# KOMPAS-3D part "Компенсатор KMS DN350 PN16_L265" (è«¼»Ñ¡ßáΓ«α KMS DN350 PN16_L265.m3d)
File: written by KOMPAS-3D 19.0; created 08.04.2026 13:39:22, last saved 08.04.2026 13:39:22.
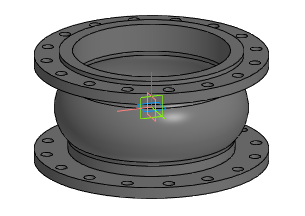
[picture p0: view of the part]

Document properties: Автор: Энергия; Полное имя файла: Z:\3.Личные\kachalov\3d для проектировщиков\7.1 Компенсатор\stp_Компенсатор KSM\Компенсатор KMS DN350 PN16_L265.m3d

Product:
- Part/product: Компенсатор KMS DN350 PN16_L265

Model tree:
1. Операция без истории:1  (labels: Компенсатор KMS DN350 PN16_L265)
